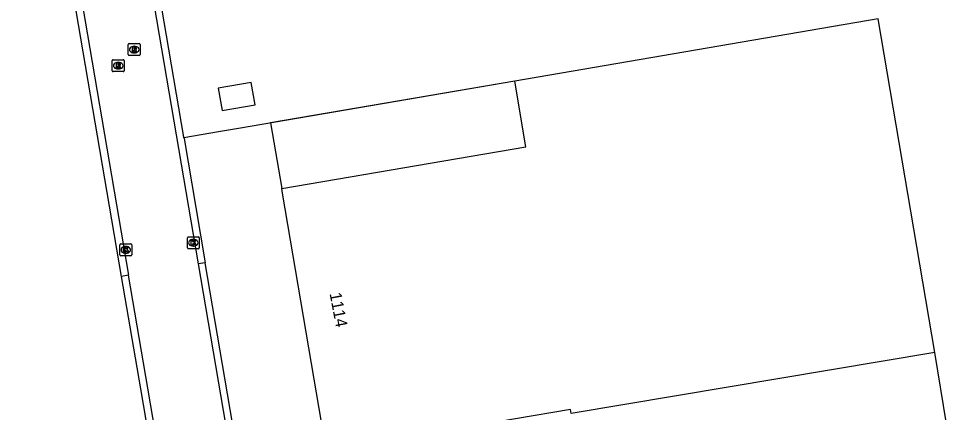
# Model space of a CAD drawing. Extents: x 154324 to 155743, y 382939 to 384183.
# Drawn here: x 154922.8 to 155000.9, y 383347.4 to 383380.6 of the extents above; entities that cross this region are included whole.
import ezdxf

# ---------------------------------------------------------------- set-up
doc = ezdxf.new("R2010")
doc.units = 0
for name, color, linetype in [('IMGEO_Grasland_agrarisch', 7, 'Continuous'), ('IMGEO_Kolk', 7, 'Continuous'), ('IMGEO_Lage_trafo', 7, 'Continuous'), ('IMGEO_Pand', 7, 'Continuous'), ('IMGEO_Pand_nummerreeks', 7, 'Continuous'), ('IMGEO_Pand_overbouw', 7, 'Continuous'), ('IMGEO_Parkeervlak_open', 7, 'Continuous'), ('IMGEO_Rijbaan_lokaal_gesloten', 7, 'Continuous'), ('IMGEO_Rijbaan_lokaal_open', 7, 'Continuous'), ('IMGEO_Rioolput', 7, 'Continuous')]:
    doc.layers.add(name, color=color, linetype=linetype)

msp = doc.modelspace()

# ---------------------------------------------------------------- linework, layer by layer
at = {"layer": 'IMGEO_Grasland_agrarisch'}
msp.add_lwpolyline([(155000.868, 383346.436), (154999.878, 383352.447)], dxfattribs=at)
at = {"layer": 'IMGEO_Kolk'}
for p, q in [((154936.986, 383361.271), (154936.986, 383362.123)), ((154937.061, 383362.197), (154937.913, 383362.197)), ((154937.474, 383361.977), (154937.499, 383361.977)), ((154937.987, 383362.123), (154937.987, 383361.271)), ((154931.301, 383360.675), (154931.301, 383361.527)), ((154931.376, 383361.601), (154932.228, 383361.601)), ((154931.789, 383361.381), (154931.814, 383361.381)), ((154932.302, 383361.527), (154932.302, 383360.675)), ((154937.913, 383361.197), (154937.061, 383361.197)), ((154937.497, 383361.417), (154937.472, 383361.417)), ((154932.228, 383360.601), (154931.376, 383360.601)), ((154931.812, 383360.821), (154931.787, 383360.821))]:
    msp.add_line(p, q, dxfattribs=at)
for points in [[(154936.986, 383361.271), (154936.986, 383362.123)], [(154937.061, 383362.197), (154937.913, 383362.197)], [(154937.307, 383361.897), (154937.43, 383361.897), (154937.43, 383361.746), (154937.56, 383361.897), (154937.724, 383361.897), (154937.578, 383361.746), (154937.731, 383361.497), (154937.579, 383361.497), (154937.494, 383361.661), (154937.43, 383361.594), (154937.43, 383361.497), (154937.307, 383361.497), (154937.307, 383361.897)], [(154937.987, 383362.123), (154937.987, 383361.271)], [(154931.301, 383360.675), (154931.301, 383361.527)], [(154931.376, 383361.601), (154932.228, 383361.601)], [(154931.622, 383361.301), (154931.745, 383361.301), (154931.745, 383361.15), (154931.875, 383361.301), (154932.039, 383361.301), (154931.893, 383361.15), (154932.046, 383360.901), (154931.894, 383360.901), (154931.809, 383361.065), (154931.745, 383360.998), (154931.745, 383360.901), (154931.622, 383360.901), (154931.622, 383361.301)], [(154932.302, 383361.527), (154932.302, 383360.675)], [(154937.913, 383361.197), (154937.061, 383361.197)], [(154932.228, 383360.601), (154931.376, 383360.601)]]:
    msp.add_lwpolyline(points, dxfattribs=at)
for centre, start, end in [((154937.063, 383362.121), 91.55205, 178.44795), ((154937.063, 383362.121), 91.55205, 178.44795), ((154937.911, 383362.121), 1.55205, 88.44795), ((154937.911, 383362.121), 1.55205, 88.44795), ((154931.378, 383361.525), 91.55205, 178.44795), ((154931.378, 383361.525), 91.55205, 178.44795), ((154932.226, 383361.525), 1.55205, 88.44795), ((154932.226, 383361.525), 1.55205, 88.44795), ((154937.063, 383361.273), 181.55205, 268.44795), ((154937.063, 383361.273), 181.55205, 268.44795), ((154937.911, 383361.273), 271.55205, 358.44795), ((154937.911, 383361.273), 271.55205, 358.44795), ((154931.378, 383360.677), 181.55205, 268.44795), ((154931.378, 383360.677), 181.55205, 268.44795), ((154932.226, 383360.677), 271.55205, 358.44795), ((154932.226, 383360.677), 271.55205, 358.44795)]:
    msp.add_arc(centre, 0.0765, start, end, dxfattribs=at)
for centre, major_axis, ratio, start_param, end_param in [((154937.473, 383361.697), (-0.387, 0.002), 0.722429, 4.712389, 7.853982), ((154937.498, 383361.697), (-0.39, 0.002), 0.717154, 1.570796, 4.712389), ((154931.788, 383361.101), (-0.387, 0.002), 0.722429, 4.712389, 7.853982), ((154931.813, 383361.101), (-0.39, 0.002), 0.717154, 1.570796, 4.712389)]:
    msp.add_ellipse(centre, major_axis=major_axis, ratio=ratio, start_param=start_param, end_param=end_param, dxfattribs=at)
at = {"layer": 'IMGEO_Lage_trafo'}
msp.add_lwpolyline([(154942.35, 383375.196), (154939.581, 383374.72), (154939.91, 383372.84), (154942.691, 383373.33), (154942.35, 383375.196)], dxfattribs=at)
at = {"layer": 'IMGEO_Pand'}
for points in [[(154999.878, 383352.447), (154995.109, 383380.559), (154964.539, 383375.316)], [(154948.75, 383343.779), (154944.993, 383365.869), (154944.925, 383366.268), (154965.468, 383369.782), (154964.539, 383375.316)], [(154999.878, 383352.447), (154969.278, 383347.303), (154969.219, 383347.653), (154959.969, 383346.088), (154960.036, 383345.69), (154948.75, 383343.779)]]:
    msp.add_lwpolyline(points, dxfattribs=at)
at = {"layer": 'IMGEO_Pand_overbouw'}
msp.add_lwpolyline([(154964.539, 383375.316), (154943.99, 383371.792), (154944.925, 383366.268), (154965.468, 383369.782)], close=True, dxfattribs=at)
at = {"layer": 'IMGEO_Parkeervlak_open'}
msp.add_lwpolyline([(154964.539, 383375.316), (154941.3, 383371.33), (154939.601, 383371.039), (154936.699, 383370.542)], dxfattribs=at)
at = {"layer": 'IMGEO_Rijbaan_lokaal_gesloten'}
for points in [[(154859.21, 383821.776), (154860.592, 383813.666), (154872.994, 383740.868), (154875.261, 383727.607), (154875.734, 383724.688), (154937.891, 383359.922)], [(154854.425, 383814.31), (154854.653, 383812.991), (154854.813, 383812.024), (154858.483, 383790.497), (154869.559, 383725.258), (154869.596, 383725.133), (154932.04, 383358.964)], [(154937.891, 383359.922), (154961.836, 383219.4)], [(154958.22, 383204.737), (154957.681, 383208.024), (154956.051, 383217.962), (154933.662, 383349.45), (154932.04, 383358.964)]]:
    msp.add_lwpolyline(points, dxfattribs=at)
at = {"layer": 'IMGEO_Rijbaan_lokaal_open'}
for points in [[(154936.699, 383370.542), (154936.688, 383370.604), (154886.005, 383668.098)], [(154931.446, 383358.867), (154880.326, 383658.587), (154880.297, 383658.755)], [(154936.699, 383370.542), (154936.71, 383370.477), (154937.698, 383364.674), (154938.491, 383360.02)], [(154938.491, 383360.02), (154937.891, 383359.922)], [(154962.428, 383219.494), (154942.478, 383336.616), (154938.491, 383360.02)], [(154932.04, 383358.964), (154931.446, 383358.867)], [(154957.636, 383205.007), (154955.126, 383219.621), (154933.063, 383349.385), (154931.446, 383358.867)]]:
    msp.add_lwpolyline(points, dxfattribs=at)
at = {"layer": 'IMGEO_Rioolput'}
for p, q in [((154932.012, 383377.549), (154932.012, 383378.401)), ((154932.087, 383378.475), (154932.939, 383378.475)), ((154933.013, 383378.401), (154933.013, 383377.549)), ((154932.523, 383377.695), (154932.498, 383377.695)), ((154932.5, 383378.255), (154932.525, 383378.255)), ((154930.666, 383376.191), (154930.666, 383377.043)), ((154930.741, 383377.117), (154931.593, 383377.117)), ((154931.154, 383376.897), (154931.179, 383376.897)), ((154931.667, 383377.043), (154931.667, 383376.191)), ((154932.939, 383377.475), (154932.087, 383377.475)), ((154931.593, 383376.117), (154930.741, 383376.117)), ((154931.177, 383376.337), (154931.152, 383376.337))]:
    msp.add_line(p, q, dxfattribs=at)
for points in [[(154932.012, 383377.549), (154932.012, 383378.401)], [(154932.087, 383378.475), (154932.939, 383378.475)], [(154933.013, 383378.401), (154933.013, 383377.549)], [(154932.601, 383378.173), (154932.349, 383378.175), (154932.349, 383377.775)], [(154932.349, 383377.775), (154932.473, 383377.775), (154932.473, 383377.937), (154932.484, 383377.937)], [(154932.527, 383378.094), (154932.473, 383378.094), (154932.473, 383378.013)], [(154932.473, 383378.013), (154932.525, 383378.013)], [(154932.531, 383377.908), (154932.602, 383377.775), (154932.742, 383377.775), (154932.677, 383377.901)], [(154930.666, 383376.191), (154930.666, 383377.043)], [(154930.741, 383377.117), (154931.593, 383377.117)], [(154931.255, 383376.815), (154931.003, 383376.817), (154931.003, 383376.417)], [(154931.181, 383376.736), (154931.127, 383376.736), (154931.127, 383376.655)], [(154931.667, 383377.043), (154931.667, 383376.191)], [(154932.939, 383377.475), (154932.087, 383377.475)], [(154931.593, 383376.117), (154930.741, 383376.117)], [(154931.003, 383376.417), (154931.127, 383376.417), (154931.127, 383376.579), (154931.138, 383376.579)], [(154931.127, 383376.655), (154931.179, 383376.655)], [(154931.185, 383376.55), (154931.256, 383376.417), (154931.396, 383376.417), (154931.331, 383376.543)]]:
    msp.add_lwpolyline(points, dxfattribs=at)
for centre, radius, start, end in [((154932.089, 383378.399), 0.0765, 91.55205, 178.44795), ((154932.089, 383378.399), 0.0765, 91.55205, 178.44795), ((154932.937, 383378.399), 0.0765, 1.55205, 88.44795), ((154932.937, 383378.399), 0.0765, 1.55205, 88.44795), ((154932.089, 383377.551), 0.0765, 181.55205, 268.44795), ((154932.089, 383377.551), 0.0765, 181.55205, 268.44795), ((154932.483, 383377.884), 0.0533, 26.02933, 88.69889), ((154932.509, 383378.202), 0.19, 274.7715, 282.96867), ((154932.533, 383377.998), 0.0964, 77.00612, 93.18647), ((154932.547, 383378.055), 0.0378, 276.66336, 79.67722), ((154932.6, 383378.063), 0.109, 350.36119, 89.41601), ((154932.598, 383378.063), 0.112, 277.58423, 350.98172), ((154932.582, 383377.848), 0.108, 29.51342, 73.79051), ((154932.937, 383377.551), 0.0765, 271.55205, 358.44795), ((154932.937, 383377.551), 0.0765, 271.55205, 358.44795), ((154930.743, 383377.041), 0.0765, 91.55205, 178.44795), ((154930.743, 383377.041), 0.0765, 91.55205, 178.44795), ((154931.187, 383376.64), 0.0964, 77.00612, 93.18647), ((154931.201, 383376.697), 0.0378, 276.66336, 79.67722), ((154931.254, 383376.705), 0.109, 350.36119, 89.41601), ((154931.591, 383377.041), 0.0765, 1.55205, 88.44795), ((154931.591, 383377.041), 0.0765, 1.55205, 88.44795), ((154930.743, 383376.193), 0.0765, 181.55205, 268.44795), ((154930.743, 383376.193), 0.0765, 181.55205, 268.44795), ((154931.137, 383376.526), 0.0533, 26.02933, 88.69889), ((154931.163, 383376.844), 0.19, 274.7715, 282.96867), ((154931.252, 383376.705), 0.112, 277.58423, 350.98172), ((154931.236, 383376.49), 0.108, 29.51342, 73.79051), ((154931.591, 383376.193), 0.0765, 271.55205, 358.44795), ((154931.591, 383376.193), 0.0765, 271.55205, 358.44795)]:
    msp.add_arc(centre, radius, start, end, dxfattribs=at)
for centre, major_axis, ratio, start_param, end_param in [((154932.499, 383377.975), (-0.387, 0.002), 0.722429, 4.712389, 7.853982), ((154932.524, 383377.975), (-0.39, 0.002), 0.717154, 1.570796, 4.712389), ((154931.153, 383376.617), (-0.387, 0.002), 0.722429, 4.712389, 7.853982), ((154931.178, 383376.617), (-0.39, 0.002), 0.717154, 1.570796, 4.712389)]:
    msp.add_ellipse(centre, major_axis=major_axis, ratio=ratio, start_param=start_param, end_param=end_param, dxfattribs=at)

# ---------------------------------------------------------------- texts
at = {"layer": 'IMGEO_Pand_nummerreeks'}
msp.add_text('1114', height=1, rotation=280.81673, dxfattribs=at).set_placement((154948.945, 383357.424))

doc.saveas('drawing.dxf')
